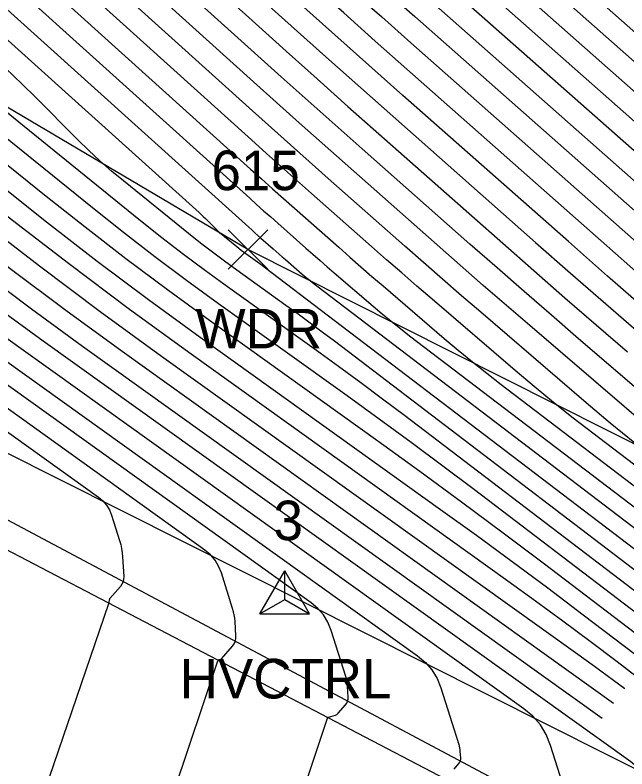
# Model space of a CAD drawing. Extents: x 1650836 to 1652450, y 332578 to 333908.
# Drawn here: x 1652312.69 to 1652343.61, y 332688.73 to 332726.84 of the extents above; entities that cross this region are included whole.
import ezdxf

# ---------------------------------------------------------------- set-up
doc = ezdxf.new("R2010")
doc.units = 0
for name, color, linetype in [('C_A', 7, 'Continuous'), ('C_I', 7, 'Continuous'), ('CPSM', 7, 'Continuous'), ('L_A', 7, 'Continuous'), ('L_I', 7, 'Continuous'), ('L_TIC', 7, 'Continuous'), ('LAWA', 7, 'Continuous'), ('LELB', 7, 'Continuous'), ('LSOGCMA', 7, 'Continuous'), ('LSOGCMI', 7, 'Continuous'), ('PET', 7, 'Continuous'), ('RGR', 7, 'Continuous')]:
    doc.layers.add(name, color=color, linetype=linetype)

msp = doc.modelspace()

# ---------------------------------------------------------------- linework, layer by layer
at = {"layer": 'CPSM'}
for p, q in [((1652325.068, 332696.575), (1652326.318, 332698.74)), ((1652327.568, 332696.575), (1652326.318, 332698.74)), ((1652326.319, 332697.296), (1652326.318, 332698.74)), ((1652325.068, 332696.575), (1652326.319, 332697.296)), ((1652326.319, 332697.296), (1652326.319, 332697.296)), ((1652326.319, 332697.296), (1652327.568, 332696.575)), ((1652325.068, 332696.575), (1652327.568, 332696.575))]:
    msp.add_line(p, q, dxfattribs=at)
at = {"layer": 'L_TIC'}
for points in [[(1652323.46, 332713.991), (1652325.46, 332715.991)], [(1652325.46, 332713.991), (1652323.46, 332715.991)]]:
    msp.add_lwpolyline(points, dxfattribs=at)
at = {"layer": 'LAWA'}
msp.add_lwpolyline([(1652408.76, 332665.713), (1652363.38, 332695.402), (1652324.46, 332714.991), (1652289.155, 332735.895), (1652253.497, 332747.946), (1652218.614, 332766.122), (1652198.198, 332775.017), (1652146.456, 332804.843), (1652136.841, 332807.592), (1652091.374, 332831.511), (1652057.601, 332848.138), (1652027.653, 332867.625)], dxfattribs=at)
at = {"layer": 'LELB'}
msp.add_lwpolyline([(1652023.441, 332859.649), (1652034.235, 332853.429), (1652052.246, 332842.357), (1652084.686, 332826.36), (1652123.711, 332804.04), (1652160.81, 332785.384), (1652195.281, 332767.897), (1652235.573, 332746.682), (1652255.289, 332735.81), (1652296.57, 332712.591), (1652348.8, 332686.345), (1652380.841, 332668.301), (1652404.073, 332656.539)], dxfattribs=at)
at = {"layer": 'LSOGCMA'}
for points in [[(1652314.342, 332744.837), (1652318.422, 332741.237), (1652319.651, 332740.149), (1652320.878, 332739.058), (1652322.102, 332737.963), (1652323.323, 332736.866), (1652328.2, 332732.468), (1652329.421, 332731.371), (1652330.645, 332730.276), (1652331.871, 332729.184), (1652333.099, 332728.095), (1652349.441, 332713.649), (1652351.143, 332712.151), (1652352.85, 332710.658), (1652354.562, 332709.172), (1652356.28, 332707.692), (1652363.161, 332701.785), (1652364.884, 332700.31), (1652366.609, 332698.839), (1652368.338, 332697.373), (1652370.071, 332695.911), (1652375.302, 332691.507)], [(1652355.967, 332694.969), (1652341.886, 332705.701), (1652340.889, 332706.472), (1652339.903, 332707.258), (1652338.929, 332708.058), (1652337.966, 332708.873), (1652333.761, 332712.482), (1652332.994, 332713.143), (1652332.229, 332713.808), (1652331.466, 332714.475), (1652330.705, 332715.144), (1652327.669, 332717.829), (1652326.91, 332718.501), (1652326.154, 332719.175), (1652325.398, 332719.85), (1652324.645, 332720.528), (1652308.083, 332735.458), (1652307.345, 332736.122), (1652306.605, 332736.784), (1652305.864, 332737.443), (1652305.12, 332738.101), (1652302.085, 332740.779)], [(1652289.634, 332734.946), (1652309.319, 332719.049), (1652312.336, 332716.649), (1652315.386, 332714.293), (1652318.47, 332711.981), (1652321.587, 332709.713), (1652337.6, 332698.24), (1652338.993, 332697.235), (1652340.377, 332696.219), (1652341.755, 332695.193), (1652343.124, 332694.157), (1652344.016, 332693.478)]]:
    msp.add_lwpolyline(points, dxfattribs=at)
at = {"layer": 'LSOGCMI'}
for points in [[(1652369.48, 332703.633), (1652368.574, 332704.408), (1652364.956, 332707.515), (1652364.052, 332708.293), (1652363.152, 332709.074), (1652362.254, 332709.859), (1652361.36, 332710.647), (1652334.11, 332734.735), (1652333.498, 332735.278), (1652332.886, 332735.822), (1652332.277, 332736.368), (1652331.668, 332736.915), (1652329.237, 332739.107), (1652328.628, 332739.654), (1652328.018, 332740.199), (1652327.407, 332740.743), (1652326.794, 332741.286), (1652308.573, 332757.364)], [(1652308.103, 332756.291), (1652325.12, 332741.276), (1652325.856, 332740.624), (1652326.59, 332739.971), (1652327.323, 332739.316), (1652328.054, 332738.659), (1652330.975, 332736.026), (1652331.706, 332735.368), (1652332.438, 332734.713), (1652333.172, 332734.059), (1652333.908, 332733.407), (1652358.976, 332711.248), (1652360.032, 332710.317), (1652361.092, 332709.391), (1652362.154, 332708.469), (1652363.221, 332707.55), (1652367.492, 332703.884), (1652368.561, 332702.968), (1652369.632, 332702.055)], [(1652307.633, 332755.218), (1652323.445, 332741.266), (1652324.305, 332740.506), (1652325.162, 332739.743), (1652326.018, 332738.978), (1652326.871, 332738.21), (1652330.281, 332735.136), (1652331.134, 332734.369), (1652331.99, 332733.604), (1652332.847, 332732.84), (1652333.706, 332732.079), (1652356.592, 332711.848), (1652357.81, 332710.776), (1652359.031, 332709.708), (1652360.256, 332708.645), (1652361.485, 332707.586), (1652366.409, 332703.359), (1652367.641, 332702.304), (1652368.876, 332701.251), (1652370.113, 332700.202)], [(1652370.88, 332690.905), (1652366.515, 332694.58), (1652365.425, 332695.5), (1652364.338, 332696.422), (1652363.252, 332697.347), (1652362.169, 332698.275), (1652351.05, 332707.819), (1652348.856, 332709.71), (1652346.668, 332711.609), (1652344.488, 332713.515), (1652342.314, 332715.43), (1652332.493, 332724.111), (1652330.895, 332725.527), (1652329.3, 332726.948), (1652327.708, 332728.372), (1652326.12, 332729.8), (1652319.64, 332735.642), (1652318.119, 332737.01), (1652316.594, 332738.373), (1652315.066, 332739.733), (1652313.534, 332741.088), (1652304.813, 332748.783)], [(1652344.605, 332711.923), (1652342.627, 332713.652), (1652340.656, 332715.389), (1652332.291, 332722.783), (1652330.569, 332724.309), (1652328.851, 332725.839), (1652327.137, 332727.373), (1652325.426, 332728.911), (1652317.989, 332735.616), (1652316.58, 332736.883), (1652315.167, 332738.146), (1652313.751, 332739.406), (1652312.332, 332740.661), (1652304.343, 332747.711)], [(1652300.499, 332747.41), (1652302.003, 332746.561), (1652302.373, 332746.34), (1652302.729, 332746.1), (1652303.072, 332745.842), (1652303.403, 332745.566), (1652309.928, 332739.808), (1652311.122, 332738.751), (1652312.313, 332737.692), (1652313.501, 332736.629), (1652314.687, 332735.563), (1652324.842, 332726.409), (1652326.396, 332725.011), (1652327.953, 332723.618), (1652329.513, 332722.229), (1652331.077, 332720.843), (1652337.339, 332715.307), (1652338.907, 332713.926), (1652340.48, 332712.551), (1652342.058, 332711.182), (1652343.641, 332709.818)], [(1652349.988, 332702.915), (1652341.171, 332710.484), (1652339.792, 332711.672), (1652338.417, 332712.865), (1652337.047, 332714.063), (1652335.68, 332715.267), (1652330.225, 332720.089), (1652328.862, 332721.297), (1652327.503, 332722.507), (1652326.146, 332723.721), (1652324.793, 332724.938), (1652313.036, 332735.537), (1652311.962, 332736.502), (1652310.886, 332737.465), (1652309.807, 332738.424), (1652308.726, 332739.381), (1652302.933, 332744.493), (1652302.574, 332744.793), (1652302.202, 332745.073), (1652301.815, 332745.333), (1652301.414, 332745.573), (1652299.782, 332746.495), (1652299.38, 332746.733)], [(1652303.571, 332746.891), (1652303.873, 332746.638), (1652311.13, 332740.235), (1652312.436, 332739.079), (1652313.74, 332737.919), (1652315.041, 332736.756), (1652316.338, 332735.589), (1652324.891, 332727.879), (1652326.645, 332726.302), (1652328.402, 332724.729), (1652330.164, 332723.16), (1652331.929, 332721.596), (1652338.997, 332715.348), (1652340.767, 332713.789), (1652342.543, 332712.237), (1652344.324, 332710.691)], [(1652315.818, 332746.509), (1652321.771, 332741.256), (1652322.754, 332740.387), (1652323.734, 332739.514), (1652324.712, 332738.64), (1652325.688, 332737.762), (1652329.588, 332734.247), (1652330.563, 332733.37), (1652331.541, 332732.494), (1652332.521, 332731.622), (1652333.504, 332730.751), (1652354.209, 332712.448), (1652355.587, 332711.234), (1652356.971, 332710.025), (1652358.358, 332708.82), (1652359.75, 332707.621), (1652365.327, 332702.834), (1652366.722, 332701.639), (1652368.121, 332700.447), (1652369.522, 332699.259), (1652370.926, 332698.074), (1652376.723, 332693.194)], [(1652376.013, 332692.35), (1652370.499, 332696.992), (1652368.93, 332698.316), (1652367.365, 332699.643), (1652365.803, 332700.975), (1652364.244, 332702.31), (1652358.015, 332707.657), (1652356.46, 332708.996), (1652354.91, 332710.342), (1652353.365, 332711.692), (1652351.825, 332713.049), (1652333.302, 332729.423), (1652332.196, 332730.403), (1652331.093, 332731.385), (1652329.992, 332732.37), (1652328.894, 332733.358), (1652324.506, 332737.314), (1652323.407, 332738.301), (1652322.306, 332739.286), (1652321.202, 332740.268), (1652320.096, 332741.247), (1652315.08, 332745.673)], [(1652313.604, 332744.001), (1652316.747, 332741.227), (1652318.1, 332740.03), (1652319.45, 332738.829), (1652320.796, 332737.625), (1652322.14, 332736.417), (1652327.507, 332731.579), (1652328.85, 332730.371), (1652330.196, 332729.166), (1652331.545, 332727.965), (1652332.897, 332726.767), (1652347.058, 332714.25), (1652348.92, 332712.609), (1652350.789, 332710.975), (1652352.664, 332709.348), (1652354.544, 332707.728), (1652362.079, 332701.26), (1652363.964, 332699.646), (1652365.854, 332698.035), (1652367.747, 332696.43), (1652369.644, 332694.829), (1652374.592, 332690.663)], [(1652312.866, 332743.164), (1652315.073, 332741.217), (1652316.549, 332739.911), (1652318.022, 332738.601), (1652319.491, 332737.287), (1652320.957, 332735.969), (1652326.813, 332730.69), (1652328.279, 332729.372), (1652329.748, 332728.057), (1652331.22, 332726.746), (1652332.695, 332725.439), (1652344.674, 332714.85), (1652346.698, 332713.067), (1652348.729, 332711.292), (1652350.766, 332709.524), (1652352.809, 332707.763), (1652361.208, 332700.554), (1652363.151, 332698.89), (1652365.097, 332697.231), (1652367.048, 332695.577), (1652369.003, 332693.927), (1652373.882, 332689.819)], [(1652345.138, 332705.624), (1652338.701, 332711.15), (1652337.526, 332712.163), (1652336.354, 332713.179), (1652335.186, 332714.2), (1652334.022, 332715.226), (1652329.373, 332719.336), (1652328.212, 332720.365), (1652327.053, 332721.396), (1652325.897, 332722.431), (1652324.744, 332723.468), (1652311.385, 332735.511), (1652310.423, 332736.376), (1652309.459, 332737.238), (1652308.493, 332738.097), (1652307.524, 332738.954), (1652303.375, 332742.615)], [(1652344.004, 332705.205), (1652342.771, 332706.218), (1652341.552, 332707.248), (1652336.231, 332711.816), (1652335.26, 332712.653), (1652334.291, 332713.494), (1652333.326, 332714.338), (1652332.364, 332715.185), (1652328.521, 332718.582), (1652327.561, 332719.433), (1652326.603, 332720.286), (1652325.648, 332721.141), (1652324.694, 332721.998), (1652309.734, 332735.485), (1652308.884, 332736.249), (1652308.032, 332737.011), (1652307.178, 332737.77), (1652306.322, 332738.528), (1652302.73, 332741.697)], [(1652278.331, 332740.9), (1652280.56, 332739.185), (1652281.007, 332738.844), (1652281.458, 332738.507), (1652281.911, 332738.174), (1652282.367, 332737.845), (1652284.199, 332736.539), (1652284.655, 332736.209), (1652285.106, 332735.874), (1652285.554, 332735.533), (1652285.997, 332735.187), (1652289.168, 332732.679), (1652289.842, 332732.144), (1652290.516, 332731.607), (1652291.188, 332731.069), (1652291.859, 332730.528), (1652306.919, 332718.366), (1652309.668, 332716.179), (1652312.447, 332714.032), (1652315.257, 332711.926), (1652318.098, 332709.859), (1652342.937, 332692.063)], [(1652301.44, 332739.861), (1652303.918, 332737.674), (1652304.549, 332737.116), (1652305.178, 332736.557), (1652305.806, 332735.995), (1652306.432, 332735.432), (1652324.596, 332719.058), (1652325.149, 332718.56), (1652325.704, 332718.064), (1652326.26, 332717.569), (1652326.817, 332717.075), (1652329.047, 332715.104), (1652329.606, 332714.612), (1652330.166, 332714.122), (1652330.728, 332713.634), (1652331.292, 332713.148), (1652334.38, 332710.497), (1652335.087, 332709.899), (1652335.803, 332709.311), (1652336.527, 332708.734), (1652337.259, 332708.167), (1652354.675, 332694.893)], [(1652300.795, 332738.943), (1652302.716, 332737.247), (1652303.234, 332736.789), (1652303.751, 332736.329), (1652304.267, 332735.868), (1652304.781, 332735.406), (1652324.547, 332717.588), (1652324.9, 332717.27), (1652325.254, 332716.953), (1652325.609, 332716.637), (1652325.965, 332716.322), (1652327.389, 332715.063), (1652327.745, 332714.749), (1652328.103, 332714.436), (1652328.462, 332714.124), (1652328.822, 332713.814), (1652330.794, 332712.122), (1652331.245, 332711.74), (1652331.702, 332711.364), (1652332.165, 332710.996), (1652332.632, 332710.634), (1652353.384, 332694.818)], [(1652345.548, 332695.49), (1652335.906, 332702.839), (1652334.311, 332704.045), (1652332.707, 332705.24), (1652331.094, 332706.423), (1652329.473, 332707.593), (1652322.97, 332712.253), (1652321.352, 332713.429), (1652319.753, 332714.629), (1652318.17, 332715.851), (1652316.606, 332717.096), (1652307.185, 332724.704), (1652306.001, 332725.686), (1652304.845, 332726.7), (1652303.717, 332727.745), (1652302.617, 332728.821), (1652297.102, 332734.363), (1652296.587, 332734.846), (1652296.043, 332735.291), (1652295.47, 332735.698), (1652294.867, 332736.065), (1652292.331, 332737.496)], [(1652345.038, 332694.819), (1652339.446, 332699.081), (1652337.358, 332700.66), (1652335.258, 332702.225), (1652333.146, 332703.773), (1652331.023, 332705.306), (1652322.509, 332711.406), (1652320.392, 332712.946), (1652318.297, 332714.517), (1652316.226, 332716.117), (1652314.177, 332717.747), (1652300.17, 332729.058), (1652299.447, 332729.658), (1652298.741, 332730.278), (1652298.052, 332730.916), (1652297.38, 332731.573), (1652294.01, 332734.959), (1652293.696, 332735.255), (1652293.363, 332735.526), (1652293.013, 332735.775), (1652292.644, 332735.999), (1652291.096, 332736.873)], [(1652349.509, 332694.591), (1652328.827, 332710.355), (1652328.218, 332710.815), (1652327.606, 332711.271), (1652326.991, 332711.722), (1652326.372, 332712.169), (1652323.891, 332713.946), (1652323.274, 332714.395), (1652322.664, 332714.853), (1652322.06, 332715.319), (1652321.463, 332715.794), (1652318.163, 332718.459), (1652317.566, 332718.955), (1652316.983, 332719.466), (1652316.414, 332719.993), (1652315.86, 332720.535), (1652313.669, 332722.736), (1652313.118, 332723.283), (1652312.56, 332723.822), (1652311.994, 332724.353), (1652311.421, 332724.876), (1652299.828, 332735.327)], [(1652301.479, 332735.354), (1652321.99, 332716.864), (1652322.098, 332716.764), (1652322.205, 332716.664), (1652322.311, 332716.562), (1652322.415, 332716.458), (1652322.83, 332716.041), (1652322.935, 332715.938), (1652323.043, 332715.839), (1652323.154, 332715.742), (1652323.267, 332715.648), (1652323.892, 332715.143), (1652324.005, 332715.053), (1652324.119, 332714.965), (1652324.235, 332714.878), (1652324.352, 332714.793), (1652324.822, 332714.456), (1652324.939, 332714.372), (1652325.056, 332714.286), (1652325.172, 332714.2), (1652325.287, 332714.113), (1652350.8, 332694.667)], [(1652303.13, 332735.38), (1652324.497, 332716.117), (1652324.651, 332715.98), (1652324.804, 332715.842), (1652324.958, 332715.705), (1652325.112, 332715.568), (1652325.73, 332715.022), (1652325.885, 332714.886), (1652326.04, 332714.75), (1652326.196, 332714.615), (1652326.352, 332714.48), (1652327.208, 332713.746), (1652327.403, 332713.58), (1652327.602, 332713.418), (1652327.802, 332713.258), (1652328.005, 332713.101), (1652352.092, 332694.742)], [(1652292.386, 332734.087), (1652292.636, 332733.855), (1652292.892, 332733.631), (1652293.155, 332733.413), (1652311.748, 332718.398), (1652314.281, 332716.383), (1652316.842, 332714.405), (1652319.431, 332712.464), (1652322.048, 332710.56), (1652334.195, 332701.856), (1652336.011, 332700.545), (1652337.817, 332699.221), (1652339.613, 332697.883), (1652341.399, 332696.532), (1652344.527, 332694.149)], [(1652290.746, 332732.737), (1652307.879, 332718.902), (1652310.882, 332716.512), (1652313.919, 332714.166), (1652316.99, 332711.864), (1652320.094, 332709.606), (1652341.005, 332694.624), (1652341.974, 332693.924), (1652342.938, 332693.217), (1652343.499, 332692.799)], [(1652348.331, 332694.429), (1652332.366, 332706.597), (1652331.265, 332707.43), (1652330.157, 332708.255), (1652329.043, 332709.072), (1652327.923, 332709.881), (1652323.43, 332713.1), (1652322.313, 332713.912), (1652321.208, 332714.741), (1652320.115, 332715.585), (1652319.034, 332716.445), (1652313.059, 332721.27), (1652311.978, 332722.167), (1652310.923, 332723.093), (1652309.893, 332724.047), (1652308.889, 332725.029), (1652304.103, 332729.838)], [(1652292.025, 332729.082), (1652292.971, 332728.319), (1652305.96, 332717.831), (1652308.454, 332715.846), (1652310.975, 332713.899), (1652313.525, 332711.987), (1652316.102, 332710.112), (1652342.358, 332691.301)], [(1652344.307, 332688.666), (1652343.808, 332689.085), (1652314.106, 332710.366), (1652311.792, 332712.049), (1652309.503, 332713.765), (1652307.239, 332715.514), (1652305, 332717.295), (1652294.084, 332726.111), (1652292.861, 332727.096), (1652291.636, 332728.077)], [(1652340.828, 332686.526), (1652339.757, 332689.916), (1652339.536, 332690.466), (1652339.237, 332690.96), (1652338.86, 332691.397), (1652338.406, 332691.779), (1652312.11, 332710.619), (1652310.06, 332712.111), (1652308.031, 332713.631), (1652306.025, 332715.181), (1652304.041, 332716.76), (1652295.197, 332723.902), (1652293.698, 332725.109), (1652292.196, 332726.313)], [(1652304.126, 332711.632), (1652316.912, 332702.471), (1652317.133, 332702.286), (1652317.316, 332702.073), (1652317.462, 332701.833), (1652317.569, 332701.565), (1652317.974, 332700.283), (1652318.032, 332700.08), (1652318.076, 332699.873), (1652318.108, 332699.665), (1652318.126, 332699.454), (1652318.183, 332698.467), (1652318.178, 332698.328), (1652318.148, 332698.198), (1652318.093, 332698.076), (1652318.013, 332697.963), (1652317.485, 332697.346), (1652317.471, 332697.327), (1652317.46, 332697.307), (1652317.452, 332697.285), (1652317.447, 332697.262), (1652317.432, 332697.167), (1652317.428, 332697.143), (1652317.423, 332697.119), (1652317.417, 332697.096), (1652317.41, 332697.073), (1652314.187, 332687.608)], [(1652320.734, 332687.622), (1652322.945, 332694.193), (1652322.953, 332694.209), (1652322.964, 332694.223), (1652322.978, 332694.233), (1652322.995, 332694.24), (1652323.068, 332694.261), (1652323.086, 332694.268), (1652323.102, 332694.277), (1652323.117, 332694.288), (1652323.13, 332694.302), (1652323.677, 332694.941), (1652323.759, 332695.057), (1652323.816, 332695.181), (1652323.846, 332695.314), (1652323.851, 332695.456), (1652323.809, 332696.181), (1652323.794, 332696.35), (1652323.769, 332696.516), (1652323.733, 332696.681), (1652323.687, 332696.844), (1652323.116, 332698.653), (1652322.98, 332698.991), (1652322.796, 332699.295), (1652322.565, 332699.564), (1652322.286, 332699.798), (1652306.122, 332711.379)], [(1652327.099, 332687.157), (1652328.479, 332691.305), (1652328.486, 332691.321), (1652328.496, 332691.333), (1652328.509, 332691.343), (1652328.524, 332691.349), (1652328.88, 332691.454), (1652328.921, 332691.469), (1652328.958, 332691.489), (1652328.992, 332691.515), (1652329.022, 332691.546), (1652329.393, 332691.979), (1652329.455, 332692.066), (1652329.497, 332692.159), (1652329.52, 332692.259), (1652329.523, 332692.365), (1652329.492, 332692.908), (1652329.481, 332693.034), (1652329.462, 332693.159), (1652329.435, 332693.283), (1652329.401, 332693.405), (1652328.663, 332695.74), (1652328.499, 332696.149), (1652328.277, 332696.516), (1652327.997, 332696.842), (1652327.659, 332697.125), (1652308.118, 332711.125)], [(1652310.114, 332710.872), (1652333.033, 332694.452), (1652333.429, 332694.119), (1652333.757, 332693.738), (1652334.017, 332693.308), (1652334.21, 332692.828), (1652335.114, 332689.965), (1652335.137, 332689.884), (1652335.155, 332689.802), (1652335.167, 332689.719), (1652335.175, 332689.635), (1652335.196, 332689.274), (1652335.193, 332689.204), (1652335.178, 332689.137), (1652335.15, 332689.075), (1652335.109, 332689.018), (1652334.862, 332688.729)]]:
    msp.add_lwpolyline(points, dxfattribs=at)
at = {"layer": 'PET'}
msp.add_lwpolyline([(1651782.185, 332994.087), (1651800.504, 332980.945), (1651823.969, 332965.234), (1651861.092, 332941.311), (1651895.497, 332920.881), (1651932.1, 332899.878), (1651964.344, 332882.546), (1651997.084, 332865.287), (1652030.302, 332847.665), (1652049.548, 332837.673), (1652081.974, 332820.953), (1652121.026, 332800.401), (1652157.819, 332781.161), (1652191.945, 332763.077), (1652232.596, 332742.33), (1652251.93, 332731.59), (1652295.202, 332708.727), (1652345.726, 332682.336), (1652379.152, 332664.868), (1652402.111, 332652.828)], dxfattribs=at)
at = {"layer": 'RGR'}
msp.add_lwpolyline([(1652023.441, 332859.649), (1652024.915, 332854.382), (1652030.806, 332848.332), (1652049.928, 332838.521), (1652082.838, 332821.514), (1652121.63, 332801.012), (1652157.949, 332781.905), (1652192.709, 332763.821), (1652232.753, 332742.853), (1652252.846, 332732.22), (1652295.713, 332710.152), (1652346.443, 332683.145), (1652379.801, 332666.008), (1652402.772, 332654.006)], dxfattribs=at)

# ---------------------------------------------------------------- texts
at = {"layer": 'C_A'}
msp.add_text('HVCTRL', height=2, dxfattribs=at).set_placement((1652321.012, 332692.296))
at = {"layer": 'C_I'}
msp.add_text('3', height=2, dxfattribs=at).set_placement((1652325.752, 332700.296))
at = {"layer": 'L_A'}
msp.add_text('WDR', height=2, dxfattribs=at).set_placement((1652321.822, 332709.991))
at = {"layer": 'L_I'}
msp.add_text('615', height=2, dxfattribs=at).set_placement((1652322.617, 332717.991))

doc.saveas('drawing.dxf')
